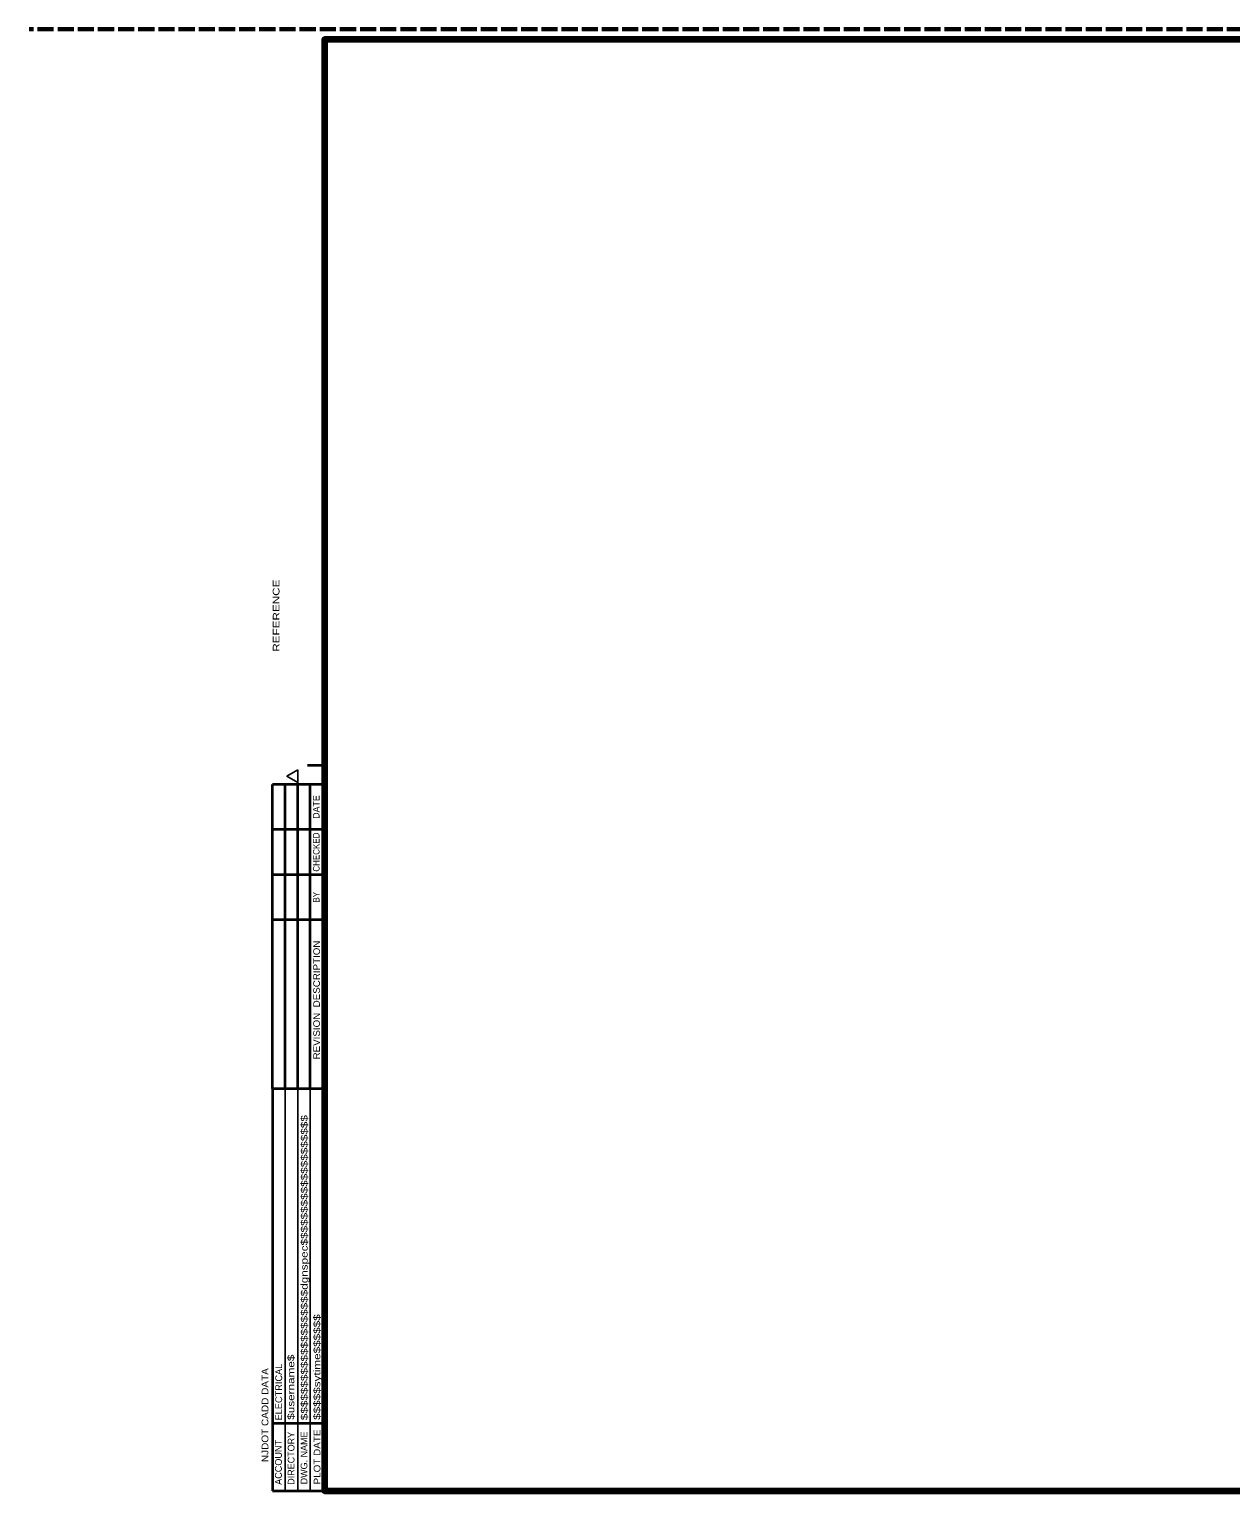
# Model space of a CAD drawing. Extents: x 168203 to 169863, y 223196 to 223870.
# Drawn here: x 169095.8 to 169229.9, y 223368.6 to 223531.7 of the extents above; entities that cross this region are included whole.
import ezdxf
from ezdxf.enums import TextEntityAlignment as Align

# ---------------------------------------------------------------- set-up
doc = ezdxf.new("R2010")
doc.units = 0
doc.header["$LTSCALE"] = 0.3
doc.linetypes.add('LONG_DASHED', pattern=[7.5, 6, -1.5])
doc.layers.add('1', color=7, linetype='Continuous', lineweight=13)
doc.layers.add('25', color=7, linetype='Continuous', lineweight=35)

msp = doc.modelspace()

# ---------------------------------------------------------------- linework, layer by layer
at = {"layer": '1', "linetype": 'LONG_DASHED', "lineweight": 60}
msp.add_line((169364.0333, 223531.7489), (169095.8093, 223531.7489), dxfattribs=at)
at = {"layer": '1', "lineweight": 35}
for p, q in [((169126.8633, 223449.6089), (169128.7833, 223449.6089)), ((169122.946, 223413.5004), (169128.7833, 223413.5004)), ((169122.946, 223413.5004), (169122.946, 223368.6089)), ((169122.946, 223376.145), (169128.7833, 223376.145)), ((169122.946, 223368.6089), (169128.7833, 223368.6089))]:
    msp.add_line(p, q, dxfattribs=at)
at = {"layer": '1', "lineweight": 25}
for p, q in [((169124.3646, 223368.6089), (169124.3646, 223413.5004)), ((169125.7833, 223368.6089), (169125.7833, 223413.5004)), ((169127.1658, 223368.6089), (169127.1658, 223413.5004))]:
    msp.add_line(p, q, dxfattribs=at)
at = {"layer": '1', "lineweight": 158}
msp.add_lwpolyline([(169361.2833, 223368.6089), (169361.2833, 223530.6089), (169128.7833, 223530.6089), (169128.7833, 223368.6089)], close=True, dxfattribs=at)
at = {"layer": '25'}
for p, q in [((169128.7833, 223447.4402), (169122.946, 223447.4402)), ((169122.946, 223413.5004), (169122.946, 223447.4402)), ((169124.3646, 223413.5004), (169124.3646, 223447.4402)), ((169125.7833, 223413.5004), (169125.7833, 223447.4402)), ((169127.1658, 223413.5004), (169127.1658, 223447.4402)), ((169128.7833, 223442.4071), (169122.946, 223442.4071)), ((169128.7833, 223437.3739), (169122.946, 223437.3739)), ((169128.7833, 223432.3408), (169122.946, 223432.3408)), ((169128.5845, 223432.3408), (169127.1658, 223432.3408))]:
    msp.add_line(p, q, dxfattribs=at)
at = {"layer": '25', "lineweight": 25}
msp.add_lwpolyline([(169125.7923, 223449.0667), (169124.5725, 223448.3619), (169125.7923, 223447.6571)], close=True, dxfattribs=at)

# ---------------------------------------------------------------- texts
at = {"layer": '1'}
for s, height, width, p in [('REFERENCE                                                              ', 0.75, 1.3, (169123.7433, 223462.2689)), ('$$$$$$$$$$$$$$$$$$$$dgnspec$$$$$$$$$$$$$$$$$$$$', 0.7526, 1.3, (169126.8767, 223376.4884)), ('$$$$$sytime$$$$$$', 0.7526, 1.3, (169128.2953, 223376.5246)), ('$username$', 0.7526, 1.3, (169125.3947, 223376.5336)), ('NJDOT CADD DATA', 0.759, 1.1, (169122.5032, 223371.8077)), ('PLOT DATE', 0.7499, 1.1, (169128.3134, 223369.3137))]:
    msp.add_text(s, height=height, rotation=90, dxfattribs=dict(at, width=width)).set_placement(p)
for s, height, p in [('ELECTRICAL', 0.768, (169124.0393, 223376.4613)), ('DIRECTORY', 0.75, (169125.4128, 223369.2776)), ('DWG. NAME', 0.75, (169126.8496, 223369.3228)), ('ACCOUNT', 0.7589, (169124.0032, 223369.2685))]:
    msp.add_text(s, height=height, rotation=90, dxfattribs=at).set_placement(p)
at = {"layer": '25'}
msp.add_text('DATE', height=0.741, rotation=90, dxfattribs=at).set_placement((169128.214, 223444.9302), align=Align.CENTER)
for s, width, p in [('CHECKED', 0.9, (169128.214, 223439.8963)), ('BY', 0.9, (169128.214, 223434.8599)), ('REVISION  DESCRIPTION', 1.1, (169128.2502, 223423.3891))]:
    msp.add_text(s, height=0.741, rotation=90, dxfattribs=dict(at, width=width)).set_placement(p, align=Align.CENTER)

doc.saveas('drawing.dxf')
